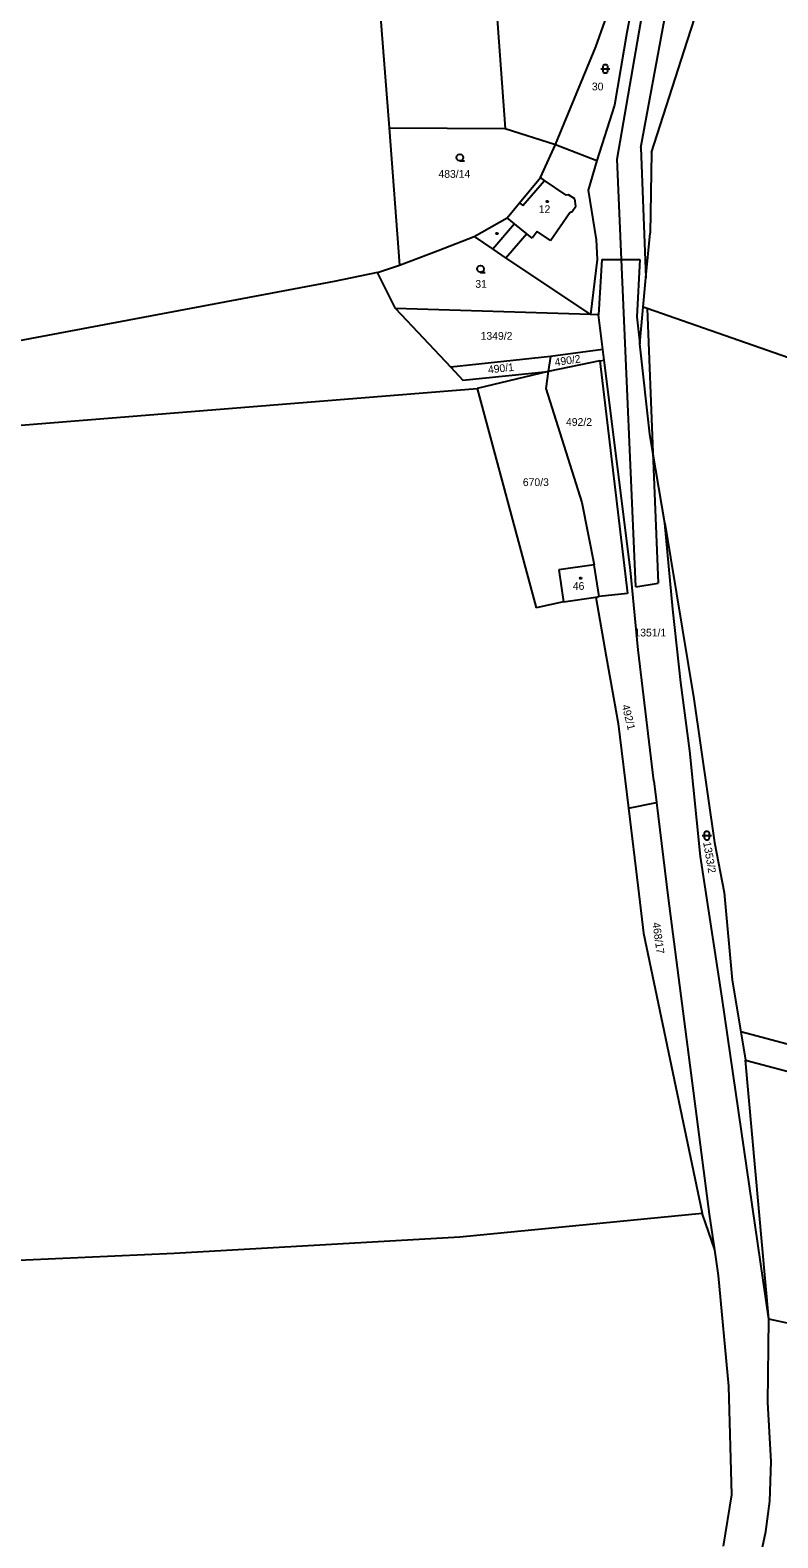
# Model space of a CAD drawing. Extents: x -845995 to -842497, y -1063614 to -1059680.
# Drawn here: x -844799.8 to -844636.3, y -1061856 to -1061526.1 of the extents above; entities that cross this region are included whole.
import ezdxf

# ---------------------------------------------------------------- set-up
doc = ezdxf.new("R2010")
doc.units = 0
for name, color, linetype in [('KN_HRANICE', 7, 'Continuous'), ('KN_KULTURY', 7, 'Continuous'), ('KN_PARCELY', 7, 'Continuous'), ('KN_SLUCKY', 7, 'Continuous'), ('KN_STAVEBNI', 7, 'Continuous')]:
    doc.layers.add(name, color=color, linetype=linetype)

# ---------------------------------------------------------------- blocks, each defined once
blk = doc.blocks.new('304')
blk.add_lwpolyline([(0, 0), (-0.38, 0.1), (-0.65, 0.37), (-0.75, 0.74), (-0.65, 1.11), (-0.38, 1.38), (-0.01, 1.48), (0.36, 1.38), (0.63, 1.11), (0.73, 0.73), (0.63, 0.35), (0.36, 0.08), (-0.02, -0.02), (0.98, -0.02)])
blk = doc.blocks.new('316')
for points in [[(-1, 1), (0.27, 1), (1, 1)], [(-0.5, 1.5), (-0.4, 1.79), (-0.15, 1.97), (0.16, 1.97), (0.41, 1.79), (0.51, 1.5), (0.51, 0.5), (0.41, 0.21), (0.16, 0.03), (-0.15, 0.03), (-0.4, 0.21), (-0.5, 0.5), (-0.5, 1.5)]]:
    blk.add_lwpolyline(points)
blk = doc.blocks.new('402')
blk.add_lwpolyline([(0.09, 0.15), (0.18, 0), (0.09, -0.15), (-0.09, -0.15), (-0.18, 0), (-0.09, 0.15), (0.09, 0.15)])

msp = doc.modelspace()

# ---------------------------------------------------------------- linework, layer by layer
at = {"layer": 'KN_HRANICE'}
for p, q in [((-844700.84, -1061479.9), (-844695.93, -1061547.63)), ((-844726.14, -1061484.58), (-844721.31, -1061547.47)), ((-844676.11, -1061529.78), (-844669.25, -1061510.34)), ((-844656.75, -1061530.65), (-844650.67, -1061511.68)), ((-844667, -1061514.65), (-844669.29, -1061526.62)), ((-844669.29, -1061526.62), (-844671.98, -1061542.55)), ((-844684.89, -1061551.1), (-844676.11, -1061529.78)), ((-844663.88, -1061552.91), (-844656.75, -1061530.65)), ((-844671.98, -1061542.55), (-844675.88, -1061554.66)), ((-844721.31, -1061547.47), (-844719.04, -1061577.54)), ((-844721.31, -1061547.47), (-844695.93, -1061547.63)), ((-844695.93, -1061547.63), (-844684.89, -1061551.1)), ((-844688.22, -1061558.36), (-844684.89, -1061551.1)), ((-844684.89, -1061551.1), (-844675.88, -1061554.66)), ((-844663.88, -1061552.91), (-844664.2, -1061570.52)), ((-844675.88, -1061554.66), (-844677.76, -1061561.12)), ((-844692.75, -1061563.86), (-844688.22, -1061558.36)), ((-844677.76, -1061561.12), (-844675.98, -1061571.96)), ((-844695.51, -1061567.21), (-844692.75, -1061563.86)), ((-844702.71, -1061571.23), (-844695.51, -1061567.21)), ((-844710.57, -1061574.35), (-844702.71, -1061571.23)), ((-844702.71, -1061571.23), (-844698.65, -1061574.01)), ((-844675.98, -1061571.96), (-844675.77, -1061576.3)), ((-844665.12, -1061580.33), (-844664.2, -1061570.52)), ((-844719.04, -1061577.54), (-844710.57, -1061574.35)), ((-844698.65, -1061574.01), (-844695.79, -1061575.97)), ((-844695.79, -1061575.97), (-844677.25, -1061588.3)), ((-844675.77, -1061576.3), (-844677.25, -1061588.3)), ((-844674.74, -1061576.3), (-844675.5, -1061588.38)), ((-844674.74, -1061576.3), (-844670.48, -1061576.3)), ((-844670.48, -1061576.3), (-844666.43, -1061576.3)), ((-844666.43, -1061576.3), (-844667.1, -1061588.8)), ((-844723.83, -1061579.1), (-844733.32, -1061581.08)), ((-844723.83, -1061579.1), (-844719.04, -1061577.54)), ((-844719.87, -1061587.02), (-844723.83, -1061579.1)), ((-844733.32, -1061581.08), (-844847.74, -1061602.71)), ((-844665.71, -1061586.69), (-844665.12, -1061580.33)), ((-844677.25, -1061588.3), (-844719.87, -1061587.02)), ((-844719.87, -1061587.02), (-844707.78, -1061599.88)), ((-844675.5, -1061588.38), (-844677.25, -1061588.3)), ((-844674.55, -1061596.01), (-844675.5, -1061588.38)), ((-844667.1, -1061588.8), (-844666.46, -1061594.72)), ((-844666.46, -1061594.72), (-844665.71, -1061586.69)), ((-844664.85, -1061586.99), (-844665.71, -1061586.69)), ((-844633.94, -1061597.82), (-844664.85, -1061586.99)), ((-844674.55, -1061596.01), (-844686.03, -1061597.5)), ((-844674.27, -1061598.28), (-844674.55, -1061596.01)), ((-844664.26, -1061614.5), (-844666.46, -1061594.72)), ((-844686.03, -1061597.5), (-844707.78, -1061599.88)), ((-844686.03, -1061597.5), (-844686.52, -1061600.77)), ((-844675.23, -1061598.44), (-844686.52, -1061600.77)), ((-844675.23, -1061598.44), (-844674.27, -1061598.28)), ((-844675.23, -1061598.44), (-844669.19, -1061649.38)), ((-844668.53, -1061644.27), (-844674.27, -1061598.28)), ((-844707.78, -1061599.88), (-844705.14, -1061602.69)), ((-844705.14, -1061602.69), (-844686.52, -1061600.77)), ((-844686.52, -1061600.77), (-844702.03, -1061604.51)), ((-844686.52, -1061600.77), (-844687, -1061604.52)), ((-844847.67, -1061616.18), (-844702.03, -1061604.51)), ((-844702.03, -1061604.51), (-844689.16, -1061652.49)), ((-844687, -1061604.52), (-844679.16, -1061629.46)), ((-844663.59, -1061618.53), (-844664.26, -1061614.5)), ((-844661.03, -1061633.98), (-844663.59, -1061618.53)), ((-844679.16, -1061629.46), (-844676.42, -1061643.1)), ((-844659.25, -1061652.78), (-844661.03, -1061633.98)), ((-844661.03, -1061633.98), (-844654.65, -1061672.42)), ((-844676.42, -1061643.1), (-844684.16, -1061644.22)), ((-844684.16, -1061644.22), (-844683.15, -1061651.22)), ((-844675.39, -1061650.03), (-844676.42, -1061643.1)), ((-844666.82, -1061661.66), (-844668.53, -1061644.27)), ((-844683.15, -1061651.22), (-844689.16, -1061652.49)), ((-844683.15, -1061651.22), (-844676.12, -1061650.14)), ((-844676.12, -1061650.14), (-844675.39, -1061650.03)), ((-844676.12, -1061650.14), (-844673.84, -1061663.14)), ((-844669.19, -1061649.38), (-844675.39, -1061650.03)), ((-844657.47, -1061668.83), (-844659.25, -1061652.78)), ((-844663.4, -1061690.33), (-844666.82, -1061661.66)), ((-844673.84, -1061663.14), (-844671.23, -1061677.79)), ((-844655.52, -1061683.8), (-844657.47, -1061668.83)), ((-844654.65, -1061672.42), (-844650.1, -1061703.82)), ((-844671.23, -1061677.79), (-844668.97, -1061696.33)), ((-844653.23, -1061706.89), (-844655.52, -1061683.8)), ((-844663.4, -1061690.33), (-844662.82, -1061695.12)), ((-844668.97, -1061696.33), (-844662.82, -1061695.12)), ((-844662.82, -1061695.12), (-844660.29, -1061716.05)), ((-844668.97, -1061696.33), (-844666.83, -1061713.85)), ((-844650.1, -1061703.82), (-844648, -1061714.79)), ((-844648.49, -1061737.9), (-844653.23, -1061706.89)), ((-844666.83, -1061713.85), (-844665.69, -1061723.64)), ((-844648, -1061714.79), (-844646.27, -1061733.99)), ((-844660.29, -1061716.05), (-844651.27, -1061785.12)), ((-844665.69, -1061723.64), (-844652.84, -1061784.91)), ((-844646.27, -1061733.99), (-844644.38, -1061745.28)), ((-844638.27, -1061808.11), (-844648.49, -1061737.9)), ((-844608.61, -1061754.86), (-844644.38, -1061745.28)), ((-844644.38, -1061745.28), (-844643.35, -1061751.43)), ((-844643.35, -1061751.43), (-844548.2, -1061776.97)), ((-844638.27, -1061808.11), (-844643.35, -1061751.43)), ((-844705.85, -1061790.12), (-844652.84, -1061784.91)), ((-844652.84, -1061784.91), (-844652.8, -1061785.12)), ((-844652.8, -1061785.12), (-844650.14, -1061792.98)), ((-844651.27, -1061785.12), (-844650.14, -1061792.98)), ((-844768.3, -1061793.68), (-844705.85, -1061790.12)), ((-844828.09, -1061796.43), (-844768.3, -1061793.68)), ((-844650.14, -1061792.98), (-844649.34, -1061798.57)), ((-844649.34, -1061798.57), (-844647.09, -1061822.8)), ((-844638.48, -1061826.34), (-844638.27, -1061808.11)), ((-844561.98, -1061824.56), (-844638.27, -1061808.11)), ((-844647.09, -1061822.8), (-844646.44, -1061846.57)), ((-844637.72, -1061839.25), (-844638.48, -1061826.34)), ((-844638.06, -1061847.91), (-844637.72, -1061839.25)), ((-844646.44, -1061846.57), (-844648.26, -1061857.77)), ((-844638.9, -1061854.57), (-844638.06, -1061847.91)), ((-844641.95, -1061868.66), (-844638.9, -1061854.57))]:
    msp.add_line(p, q, dxfattribs=at)
at = {"layer": 'KN_SLUCKY'}
for p, q in [((-844671.44, -1061554.37), (-844665.98, -1061522.69)), ((-844666.26, -1061551.77), (-844661.05, -1061523.77)), ((-844666.26, -1061551.77), (-844665.12, -1061580.33)), ((-844670.48, -1061576.3), (-844671.44, -1061554.37)), ((-844692.06, -1061564.45), (-844687.29, -1061558.98)), ((-844687.29, -1061558.98), (-844688.22, -1061558.36)), ((-844682.58, -1061562.2), (-844687.29, -1061558.98)), ((-844682.07, -1061562.17), (-844682.58, -1061562.2)), ((-844680.71, -1061563.03), (-844682.07, -1061562.17)), ((-844680.45, -1061564.59), (-844680.71, -1061563.03)), ((-844692.75, -1061563.86), (-844692.06, -1061564.45)), ((-844686.01, -1061572.15), (-844681.78, -1061566)), ((-844681.78, -1061566), (-844681.28, -1061565.81)), ((-844681.28, -1061565.81), (-844680.45, -1061564.59)), ((-844693.91, -1061568.47), (-844698.65, -1061574.01)), ((-844693.91, -1061568.47), (-844695.51, -1061567.21)), ((-844691.2, -1061570.69), (-844693.91, -1061568.47)), ((-844691.2, -1061570.69), (-844695.79, -1061575.97)), ((-844690.02, -1061571.62), (-844691.2, -1061570.69)), ((-844688.92, -1061570.18), (-844690.02, -1061571.62)), ((-844686.01, -1061572.15), (-844688.92, -1061570.18)), ((-844667.35, -1061647.89), (-844670.48, -1061576.3)), ((-844664.85, -1061586.99), (-844663.59, -1061618.53)), ((-844663.59, -1061618.53), (-844662.45, -1061647.1)), ((-844667.35, -1061647.89), (-844662.45, -1061647.1))]:
    msp.add_line(p, q, dxfattribs=at)
at = {"layer": 'KN_STAVEBNI'}
for p, q in [((-844692.06, -1061564.45), (-844687.29, -1061558.98)), ((-844682.58, -1061562.2), (-844687.29, -1061558.98)), ((-844682.07, -1061562.17), (-844682.58, -1061562.2)), ((-844680.71, -1061563.03), (-844682.07, -1061562.17)), ((-844680.45, -1061564.59), (-844680.71, -1061563.03)), ((-844695.51, -1061567.21), (-844692.75, -1061563.86)), ((-844692.75, -1061563.86), (-844692.06, -1061564.45)), ((-844686.01, -1061572.15), (-844681.78, -1061566)), ((-844681.78, -1061566), (-844681.28, -1061565.81)), ((-844681.28, -1061565.81), (-844680.45, -1061564.59)), ((-844693.91, -1061568.47), (-844695.51, -1061567.21)), ((-844691.2, -1061570.69), (-844693.91, -1061568.47)), ((-844690.02, -1061571.62), (-844691.2, -1061570.69)), ((-844688.92, -1061570.18), (-844690.02, -1061571.62)), ((-844686.01, -1061572.15), (-844688.92, -1061570.18)), ((-844676.42, -1061643.1), (-844684.16, -1061644.22)), ((-844684.16, -1061644.22), (-844683.15, -1061651.22)), ((-844675.39, -1061650.03), (-844676.42, -1061643.1)), ((-844683.15, -1061651.22), (-844676.12, -1061650.14)), ((-844676.12, -1061650.14), (-844675.39, -1061650.03))]:
    msp.add_line(p, q, dxfattribs=at)

# ---------------------------------------------------------------- block references
at = {"layer": 'KN_KULTURY'}
for name, p in [('316', (-844674.01, -1061535.59)), ('304', (-844705.81, -1061554.7)), ('402', (-844686.71, -1061563.61)), ('402', (-844697.69, -1061570.61)), ('304', (-844701.3, -1061579.09)), ('402', (-844679.4, -1061646)), ('316', (-844651.8, -1061703.33))]:
    msp.add_blockref(name, p, dxfattribs=at)

# ---------------------------------------------------------------- texts
at = {"layer": 'KN_PARCELY'}
for s, p in [('30', (-844676.95, -1061539.29)), ('483/14', (-844710.51, -1061558.42)), ('12', (-844688.57, -1061566.14)), ('31', (-844702.44, -1061582.48)), ('1349/2', (-844701.28, -1061593.85)), ('492/2', (-844682.61, -1061612.69)), ('670/3', (-844692.05, -1061625.86)), ('46', (-844681.12, -1061648.57)), ('1351/1', (-844667.64, -1061658.76))]:
    msp.add_text(s, height=1.7, dxfattribs=at).set_placement(p)
for s, rotation, p in [('490/1', 5.844, (-844699.6, -1061601.23)), ('490/2', 8.193, (-844684.96, -1061599.62)), ('492/1', 284.302, (-844670.45, -1061673.87)), ('1353/2', 279.775, (-844652.63, -1061703.82)), ('468/17', 277.827, (-844663.71, -1061721.42))]:
    msp.add_text(s, height=1.7, rotation=rotation, dxfattribs=at).set_placement(p)

doc.saveas('drawing.dxf')
